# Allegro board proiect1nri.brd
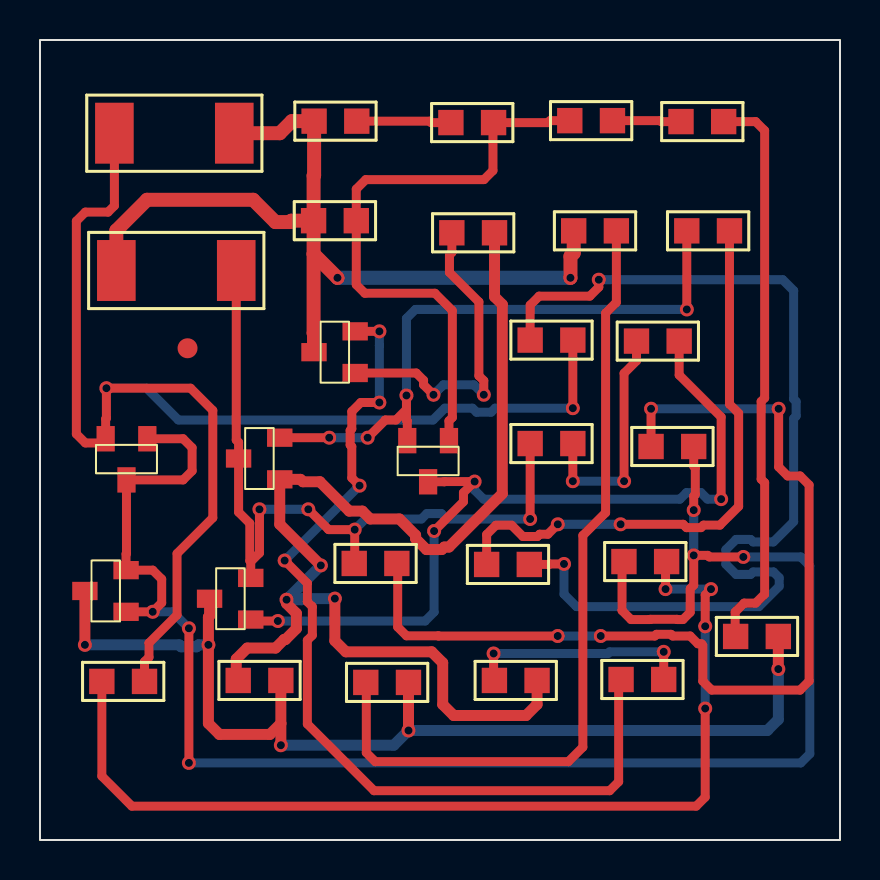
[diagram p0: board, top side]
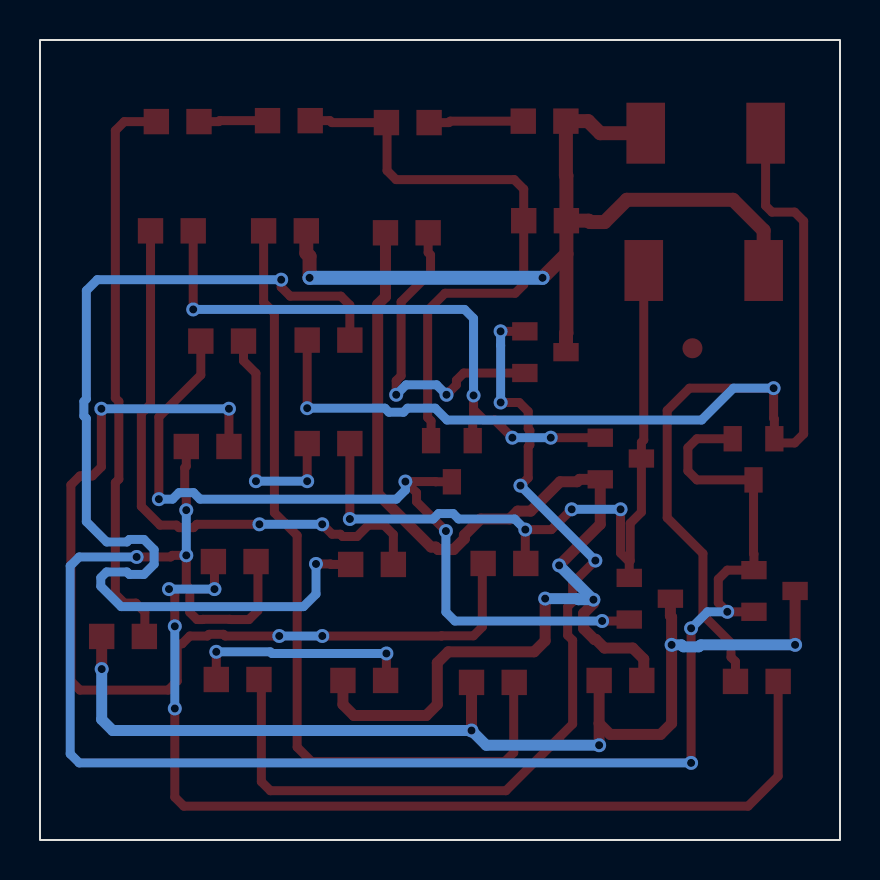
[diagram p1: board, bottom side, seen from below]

Outline 40 x 40 mm; copper layers: TOP, BOTTOM. Coordinates in mm from the lower left corner of the outline.
Outline path: rectangle 0,0 40,40

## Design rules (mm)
nets with their own width: min track width 0.45; nets N10981 N10989 N10993 N11005 N11081 N11129 N11169 N11173 N11237 N11249 N11403 N11407 N11711 N11715 N11753 N112951 N114771 N115311
nets with their own width: min track width 0.55; nets VIN VOUT
nets with their own width: min track width 0.7; nets GND

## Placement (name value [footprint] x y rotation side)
C1  1n  [SMC0805]  13.68 30.96 0 top
C2  1n  [SMC0805]  34.78 10.18 0 top
J1  CON2  [SMR2512]  3.72 35.34 0 top
J2  CON2  [SMR2512]  3.82 28.48 0 top
NOREF  -  [unnamed]  7.38 24.59 0 top
Q1  BC856B  [TO236AA]  11.99 18.03 0 top
Q2  BC856B  [TO236AA]  20.45 19.97 90 top
Q3  BC856B  [TO236AA]  5.37 20.06 90 top
Q4  BC856B  [TO236AA]  4.3 11.41 0 top
Q5  BC846B  [TO236AA]  10.54 11.02 0 top
Q6  BC856B  [TO236AA]  15.76 23.35 0 top
R1  15k  [SMR0805]  13.71 35.94 0 top
R2  820  [SMR0805]  20.55 35.87 0 top
R3  15k  [SMR0805]  26.49 35.97 0 top
R4  820  [SMR0805]  32.05 35.92 0 top
R5  100k  [SMR0805]  20.59 30.36 0 top
R6  33  [SMR0805]  26.68 30.46 0 top
R8  100  [SMR0805]  32.34 30.46 0 top
R9  150  [SMR0805]  24.51 25 0 top
R10  150  [SMR0805]  29.82 24.95 0 top
R11  10  [SMR0805]  24.51 19.82 0 top
R12  150  [SMR0805]  30.55 19.68 0 top
R13  33  [SMR0805]  15.71 13.83 0 top
R14  150  [SMR0805]  22.33 13.78 0 top
R15  150  [SMR0805]  29.2 13.92 0 top
R16  150  [SMR0805]  3.09 7.93 0 top
R17  10k  [SMR0805]  9.91 7.98 0 top
R18  470  [SMR0805]  16.29 7.88 0 top
R19  15k  [SMR0805]  22.72 7.98 0 top
R20  510  [SMR0805]  29.05 8.03 0 top

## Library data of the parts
C1 C2 = C
J1 J2 = CON2
Q1-Q4 Q6 = BC856B
Q5 = BC846B
R1-R6 R8-R20 = R

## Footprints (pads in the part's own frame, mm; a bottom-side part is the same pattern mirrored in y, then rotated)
SMC0805
  rect 1.27x1.27 smd: 1(0,0) 2(2.134,0)
SMR0805
  rect 1.27x1.27 smd: 1(0,0) 2(2.134,0)
SMR2512
  rect 1.93x3.048 smd: 1(0,0) 2(5.994,0)
TO236AA
  rect 1.27x0.914 smd: 1(0,0) 2(0,2.083) 3(-2.057,1.041)
unnamed
  round 1 smd: (0,0)

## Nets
GND: C1.1 J1.2 J2.1 Q6.3 R1.1 R6.1
VIN: Q1.1 R5.2 R17.1 R19.2
VOUT: C2.2 Q4.3 Q5.3 R17.2 R18.2
N10981: C1.2 Q2.1 R2.2 R3.1
N10989: R3.2 R4.1
N10993: C2.1 R4.2
N11005: J1.1 Q3.2(E) R9.2 R16.2
N11081: R9.1 R14.2
N11129: R15.2 R16.1
N11169: R8.2 R14.1
N11173: R1.2 R2.1
N11237: Q3.1 Q3.3 Q4.1 Q4.2(E) R12.2 R15.1
N11249: Q1.2(E) Q2.2(E) R8.1
N11403: Q2.3 Q5.1 R10.2
N11407: J2.2 Q1.3 Q5.2(E) R11.1 R13.1
N11711: Q6.1 R5.1
N11715: R19.1 R20.2
N11753: Q6.2(E) R20.1
N112951: R6.2 R18.1
N114771: R12.1 R13.2
N115311: R10.1 R11.2

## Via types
v1: diameter 0.7, hole 0.4, TOP to BOTTOM, 52 vias

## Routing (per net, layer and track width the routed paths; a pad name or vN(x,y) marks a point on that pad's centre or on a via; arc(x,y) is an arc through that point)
GND: length 44.6
  TOP w0.7: Q6.3 13.7,25.33 13.68,25.35 13.68,29.3 ; R6.1 26.68,29.35 26.52,29.18 v1(26.52,28.11) ; C1.1 12.57,30.96 12.5,30.9 11.77,30.9 10.66,32.01 5.35,32.01 3.82,30.48 J2.1 ; C1.1 13.68,29.3 ; C1.1 13.68,33.22 13.71,33.24 R1.1 12.59,35.94 11.99,35.34 J1.2 ; 13.68,29.3 v1(14.87,28.11)
  BOTTOM w0.7: v1(14.87,28.11) v1(26.52,28.11)
VIN: length 59.9
  TOP w0.55: R5.2 22.73,27.16 23.12,26.77 23.12,17.32 20.45,14.65 20.21,14.65 20.09,14.52 19.32,14.52 18.78,15.06 18.78,15.24 17.97,16.05 16.51,16.05 16.12,16.45 15.46,16.45 13.99,17.91 13.14,17.91 13.02,18.03 Q1.1 11.99,15.79 v1(14.04,13.73) ; R17.1 9.81,8.07 9.81,9.05 10.36,9.6 11.78,9.6 12.21,10.03 12.28,10.03 12.82,10.57 12.82,11.33 12.33,11.82 v1(12.33,12.02) ; v1(14.74,12.07) 14.74,9.96 15.29,9.41 19.59,9.41 20.14,8.86 20.14,6.78 20.68,6.23 24.3,6.23 24.85,6.78 R19.2
  BOTTOM w0.55: v1(14.74,12.07) 13.13,12.07 13.08,12.02 v1(12.33,12.02) v1(14.04,13.73)
VOUT: length 54.5
  TOP w0.55: R17.2 12.04,5.83 ; 12.04,5.83 11.49,5.28 8.97,5.28 8.42,5.83 v1(8.42,9.76) 8.42,11.14 8.48,11.2 Q5.3 ; 12.04,5.83 v1(12.04,4.74) ; C2.2 v1(36.92,8.55) ; Q4.3 v1(2.25,9.76) ; R18.2 18.42,6.84 18.43,6.84 v1(18.43,5.47)
  BOTTOM w0.55: v1(8.42,9.76) 7.93,9.76 7.83,9.66 7.06,9.66 6.96,9.76 v1(2.25,9.76) ; v1(36.92,8.55) 36.92,6.03 36.37,5.47 v1(18.43,5.47) 17.69,4.74 v1(12.04,4.74)
N10981: length 30.2
  TOP w0.45: R3.1 25.5,35.97 25.41,35.87 R2.2 22.65,35.84 22.65,33.47 22.2,33.02 16.29,33.02 15.81,32.54 C1.2 15.81,27.77 16.24,27.34 19.75,27.34 20.62,26.47 20.62,21.12 20.45,20.95 Q2.1
N10989: length 3.4
  TOP w0.45: R3.2 31.02,35.97 31.06,35.92 R4.1
N10993: length 28.6
  TOP w0.45: R4.2 35.78,35.92 36.23,35.47 36.23,22.1 36.06,21.93 36.06,18.04 36.23,17.87 36.23,12.29 35.78,11.85 35.21,11.85 34.76,11.39 34.76,10.2 C2.1
N11005: length 69.3
  TOP w0.45: R16.2 5.23,8.92 5.45,9.14 5.45,9.85 6.85,11.25 6.85,14.32 8.64,16.11 8.64,21.48 7.53,22.59 v1(3.32,22.59) 3.32,21.09 3.28,21.05 Q3.2 3.07,19.85 2.27,19.85 1.82,20.3 1.82,30.94 2.27,31.39 3.4,31.39 3.72,31.71 J1.1 ; R9.2 v1(26.64,21.59)
  BOTTOM w0.45: v1(3.32,22.59) 5.33,22.59 6.92,21 19.65,21 20.24,21.59 21.62,21.59 21.83,21.39 22.55,21.39 22.76,21.59 v1(26.64,21.59)
N11081: length 50.5
  TOP w0.45: R14.2 25.45,13.78 25.48,13.8 v1(26.2,13.8) ; R9.1 24.51,26.74 24.96,27.19 27.49,27.19 27.94,27.64 v1(27.94,28.02)
  BOTTOM w0.45: v1(26.2,13.8) 26.2,12.29 26.82,11.67 35.94,11.67 36.96,12.69 36.96,13.12 36.67,13.4 35.66,13.4 35.53,13.28 34.8,13.28 34.29,13.79 34.29,14.52 34.8,15.03 35.53,15.03 35.66,14.9 36.67,14.9 37.68,15.92 37.68,21.07 37.81,21.2 37.81,21.93 37.68,22.05 37.68,27.47 37.13,28.02 v1(27.94,28.02)
N11129: length 49.9
  TOP w0.45: v1(31.28,12.54) 31.28,13.87 R15.2 ; v1(33.26,10.69) 33.26,12.26 v1(33.55,12.54) ; v1(33.26,6.58) 33.26,2.14 32.81,1.69 4.59,1.69 3.09,3.19 R16.1
  BOTTOM w0.45: v1(33.26,6.58) v1(33.26,10.69) ; v1(33.55,12.54) v1(31.28,12.54)
N11169: length 29.3
  TOP w0.45: R8.2 34.47,21.79 34.93,21.34 34.93,16.68 34,15.74 33.17,15.74 33.05,15.62 32.32,15.62 32.16,15.79 v1(29.03,15.79) ; R14.1 22.33,15.28 22.8,15.74 23.58,15.74 24.14,15.18 24.87,15.18 24.98,15.29 25.39,15.29 v1(25.89,15.79)
  BOTTOM w0.45: v1(29.03,15.79) v1(25.89,15.79)
N11173: length 4.7
  TOP w0.45: R2.1 19.56,35.87 19.49,35.94 R1.2
N11237: length 86.9
  TOP w0.45: v1(35.17,14.15) 33.47,14.15 33.39,14.23 v1(32.69,14.23) 32.69,12.74 32.51,12.57 32.51,11.38 32.15,11.02 31.87,11.02 31.86,11.03 30.51,11.03 30.5,11.02 29.55,11.02 29.1,11.47 29.1,13.83 R15.1 ; R12.2 32.69,18.69 32.77,18.61 32.77,17.27 32.69,17.2 v1(32.69,16.49) ; Q3.1 7.16,20.06 7.61,19.61 7.61,18.46 7.16,18.01 Q3.3 4.32,14.32 4.3,14.3 Q4.2 5.63,13.49 6.08,13.04 6.08,11.86 v1(5.63,11.41) Q4.1 ; v1(7.45,10.59) v1(7.45,3.85)
  BOTTOM w0.45: v1(7.45,10.59) 6.62,11.41 v1(5.63,11.41) ; v1(7.45,3.85) 38.04,3.85 38.49,4.3 38.49,13.7 38.04,14.15 v1(35.17,14.15) ; v1(32.69,16.49) v1(32.69,14.23)
N11249: length 31.2
  TOP w0.45: 18.32,21.53 17.8,21 17.27,21 v1(16.38,20.12) ; 18.32,21.53 18.32,21 18.36,20.95 Q2.2 ; 18.32,21.53 v1(18.32,22.23) ; Q1.2 v1(14.46,20.12) ; R8.1 v1(32.34,26.53)
  BOTTOM w0.45: v1(18.32,22.23) 18.32,26.08 18.77,26.53 v1(32.34,26.53) ; v1(14.46,20.12) v1(16.38,20.12)
N11403: length 41.1
  TOP w0.45: v1(19.7,15.45) 21.17,16.91 21.17,17.36 v1(21.73,17.92) 20.23,17.92 20.22,17.91 Q2.3 ; Q5.1 10.61,10.95 v1(11.89,10.95) ; R10.2 31.96,23.25 34.06,21.15 v1(34.06,17.04)
  BOTTOM w0.45: v1(11.89,10.95) 19.25,10.95 19.7,11.4 v1(19.7,15.45) ; v1(34.06,17.04) 33.37,17.04 33.05,17.37 32.32,17.37 32,17.04 22.18,17.04 21.73,17.49 v1(21.73,17.92)
N11407: length 38.3
  TOP w0.45: v1(10.97,16.54) 10.97,14.35 10.54,13.91 ; R11.1 v1(24.51,16.05) ; J2.2 9.81,20 9.93,19.88 Q1.3 9.93,16.39 10.49,15.83 10.49,13.96 10.54,13.91 ; 10.54,13.91 Q5.2 ; v1(13.41,16.54) 14.43,15.52 v1(15.73,15.52) 15.73,13.85 R13.1
  BOTTOM w0.45: v1(24.51,16.05) 20.34,16.05 20.07,16.32 19.34,16.32 19.07,16.05 16.27,16.05 v1(15.73,15.52) ; v1(13.41,16.54) v1(10.97,16.54)
N11711: length 16.3
  TOP w0.45: R5.1 20.59,29.37 20.47,29.25 20.47,28.38 21.95,26.91 21.95,23.21 22.19,22.96 v1(22.19,22.26) ; Q6.1 18.81,23.35 19.18,22.98 19.18,22.76 v1(19.68,22.26)
  BOTTOM w0.45: v1(22.19,22.26) 21.69,22.76 20.17,22.76 v1(19.68,22.26)
N11715: length 11.3
  TOP w0.45: v1(22.68,9.32) 22.68,8.02 R19.1 ; R20.2 v1(31.19,9.41)
  BOTTOM w0.45: v1(22.68,9.32) 28.4,9.32 28.48,9.41 v1(31.19,9.41)
N11753: length 46.7
  TOP w0.45: R20.1 28.93,7.91 28.93,2.92 28.48,2.46 16.7,2.46 13.37,5.8 13.37,9.99 13.62,10.24 13.62,11.66 13.37,11.91 13.37,12.84 v1(12.23,13.97) ; Q6.2 v1(16.97,25.43) ; v1(15.98,17.72) 15.59,18.11 15.59,19.67 15.51,19.75 15.51,20.48 15.59,20.56 15.59,21.43 16.04,21.88 v1(16.97,21.88)
  BOTTOM w0.45: v1(16.97,21.88) 16.97,24.73 16.97,24.73 v1(16.97,25.43) ; v1(15.98,17.72) v1(12.23,13.97)
N112951: length 41.3
  TOP w0.45: R6.2 28.82,26.88 28.28,26.34 28.28,16.36 27.14,15.23 27.14,4.64 26.42,3.92 16.77,3.92 16.32,4.37 16.32,7.86 R18.1
N114771: length 49.3
  TOP w0.45: v1(25.89,10.2) 19.93,10.2 19.92,10.21 18.32,10.21 17.89,10.65 17.89,13.79 R13.2 ; v1(28.04,10.2) 30.74,10.2 30.82,10.28 31.55,10.28 31.63,10.2 32.51,10.2 32.9,9.81 33.07,9.81 33.14,9.74 33.14,7.95 33.59,7.5 38.01,7.5 38.45,7.95 38.45,17.75 38.01,18.2 37.38,18.2 36.93,18.65 v1(36.93,21.56) ; R12.1 v1(30.55,21.56)
  BOTTOM w0.45: v1(28.04,10.2) v1(25.89,10.2) ; v1(30.55,21.56) v1(36.93,21.56)
N115311: length 11.7
  TOP w0.45: v1(29.2,17.94) 29.2,23.34 29.82,23.96 R10.1 ; R11.2 v1(26.64,17.94)
  BOTTOM w0.45: v1(26.64,17.94) v1(29.2,17.94)

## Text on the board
Ref Des/Assembly Top: Negrila Robert 432C Proiect1
XSECTION_CHART: *  SURFACE | L1 TOP CONDUCTOR | *  DIELECTRIC | L2 BOTTOM CONDUCTOR | DESIGN CROSS SECTION CHART | ___________________________ | TOTAL THICKNESS 0.26416 MM | 1-2
NCLEGEND-1-2: FIGURE | FINISHED_SIZE | 0.4 | DRILL CHART: TOP to BOTTOM | ALL UNITS ARE IN MILLIMETERS | PLATED | QTY | 48
